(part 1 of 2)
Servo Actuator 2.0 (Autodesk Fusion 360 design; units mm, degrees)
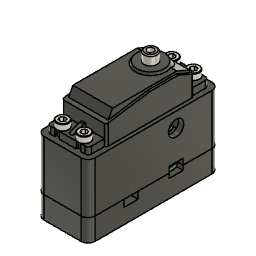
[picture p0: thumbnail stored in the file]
base_feature "Base Feature1"
base_feature "Base Feature1"
base_feature "Base Feature1"
base_feature "Base Feature1"
extrude "Extrude1" add of existing geometry blind 3.556
extrude "Extrude2" add of existing geometry blind 1
sketch "Sketch1" plane through (0, 0, 13.9918) normal (0, 0, -1) x axis (1, 0, 0)
  circle C1 centre (0, -10.25) radius 4
  circle C2 centre (0, -10.25) radius 8.7625
  dimension "d5" = 4.7625
extrude "Extrude1" new body sketch "Sketch1" along normal blind 5.675 (= "0.125 in + 2.5 mm")
extrude "Extrude3" add of existing geometry blind 3.175
combine "Combine1"
extrude "Extrude2" cut of existing geometry blind -4.7
sketch "Sketch2" plane through (0, 0, 24.9956) normal (0, 0, 1) x axis (-1, 0, 0)
  line L1 (0.8395, -12.0586) -> (1.9866, -10.4203)
  line L2 (-1.9866, -10.0797) -> (0.8395, -12.0586)
  line L3 (-0.8395, -8.4414) -> (-1.9866, -10.0797)
  line L4 (1.9866, -10.4203) -> (-0.8395, -8.4414)
  line L5 (-1.9866, -10.0797) -> (-0.8395, -8.4414)
  line L6 (0.8395, -12.0586) -> (-1.9866, -10.0797)
  line L7 (1.9866, -10.4203) -> (0.8395, -12.0586)
  line L8 (-0.8395, -8.4414) -> (1.9866, -10.4203)
  circle C1 centre (0, -10.25) radius 4
split "Split1"
copy_paste_bodies "CutPasteBodies1"
copy_paste_bodies "CutPasteBodies1"
component_from_bodies "Body->Comp1"
extrude "Extrude3" new body of existing geometry blind 2.5
delete_face "DeleteFace1"
component_from_bodies "Body->Comp1"
copy_paste "CutPaste1"
sketch "Sketch1" plane through (0, 0, 0) normal (0, 0, 1) x axis (1, 0, 0)
  line L1 (-7.25, -8.75) -> (7.25, -8.75)
  line L2 (-7.25, 8.75) -> (-7.25, -8.75)
  line L3 (7.25, 8.75) -> (-7.25, 8.75)
  line L4 (7.25, -8.75) -> (7.25, 8.75)
  line L5 (-7.25, 8.75) -> (7.25, -8.75)
  line L6 (7.25, 8.75) -> (-7.25, -8.75)
  line L7 (0, 8.75) -> (0, -8.75)
  line L8 (-2.5, -2.35) -> (2.5, -2.35)
  line L9 (-2.5, 1.45) -> (-2.5, -2.35)
  line L10 (2.5, 1.45) -> (-2.5, 1.45)
  line L11 (2.5, -2.35) -> (2.5, 1.45)
  line L12 (-2.5, 1.45) -> (2.5, -2.35)
  line L13 (2.5, 1.45) -> (-2.5, -2.35)
  line L14 (7.25, -0.45) -> (-7.25, -0.45)
  line L15 (3.75, -8.75) -> (7.25, -5.25)
  line L16 (-3.75, -8.75) -> (-7.25, -5.25)
  arc A1 centre (0, 0.1797) radius 8.5703 clockwise from (-7.25, 4.75) to (7.25, 4.75)
  circle C1 centre (6, -0.45) radius 1.5
  circle C2 centre (-6, -0.45) radius 1.5
  point P6 (0, 0)
  point P1 (0, 0)
  point P7 (0, -8.75)
  point P8 (0, 8.75)
  point P13 (0, -0.45)
  point P14 (-7.25, -0.45)
  point P15 (7.25, -0.45)
  point P16 (7.25, 4.75)
  point P17 (-7.25, 4.75)
  point P19 (7.25, 4.75)
  point P18 (-7.25, 4.75)
  point P21 (7.25, -5.25)
  point P22 (3.75, -8.75)
  point P23 (7.25, -5.25)
  point P24 (3.75, -8.75)
  point P25 (-7.25, -5.25)
  point P26 (-3.75, -8.75)
  point P27 (6, -0.45)
  point P2 (7.25, -8.75)
  point P5 (7.25, 8.75)
  horizontal L1
  perpendicular L1 L2
  parallel L1 L3
  parallel L2 L4
  coincident L5 P6
  coincident L6 P6
  coincident P1 P6
  midpoint L1 P7
  midpoint L3 P8
  horizontal L8
  perpendicular L8 L9
  parallel L8 L10
  parallel L9 L11
  coincident L12 P13
  coincident L13 P13
  coincident L7 P13
  coincident L2 P14
  coincident L4 P15
  perpendicular L4 L14
  coincident P13 L14
  coincident L4 P16
  symmetric L7 P16 P17
  coincident P8 A1
  tangent L3 A1
  coincident P16 P19
  coincident P17 P18
  coincident L4 P21
  coincident L1 P22
  coincident P21 P23
  coincident P22 P24
  symmetric L7 P23 P25
  symmetric L7 P24 P26
  coincident L14 P27
  symmetric L7 C1 C2
  dimension "d1_1" distance P2 P5 = 17.5
  dimension "d2_1" distance L2 L4 = 14.5
  dimension "d3_1" distance L1 L8 = 6.4
  dimension "d4_1" distance L3 L10 = 7.3
  dimension "d5_1" distance L9 L11 = 5
  dimension "d6_1" distance P5 P16 = 4
  dimension "d7_1" distance P2 P21 = 3.5
  dimension "d8_1" distance P2 P22 = 3.5
  dimension "d9_1" diameter C1 = 3
  dimension "d10_1" distance L11 P27 = 3.5 (= "2 mm + 1.5 mm")
extrude "Extrude1" new body sketch "Sketch1" profile of L1 L2 L4 L8 L9 L10 L11 A1 L15 L16 C1 C2 against normal blind 1.7 named "d11_1"
extrude "Extrude2" new body sketch "Sketch1" profile of L8 L9 L10 L11 along normal blind 1.5 named "d13_1"
position "Position1"
position "Position2"
position "Position3"
position "Position4"
copy_paste "CutPaste2"
work_plane "WorkPlane1" AlongDistance -21
split "Split1"
combine "Combine1"
split "Split1"
remove_body "RemoveBody2"
extrude "Extrude1" add of existing geometry blind 2.2
extrude "Extrude2" add of existing geometry blind 1
extrude "Extrude3" cut of existing geometry blind -0.2
extrude "Extrude4" add of existing geometry blind 0.2
work_plane "WorkPlane2"
extrude "Extrude4" cut of existing geometry blind -0.2063 (= "( 2 mm - ( ( 1 / 16 ) * 1 in ) ) / -2")
extrude "Extrude5" cut of existing geometry blind -0.2063 (= "( 2 mm - ( ( 1 / 16 ) * 1 in ) ) / -2")
extrude "Extrude5" add of existing geometry blind 0.2063 (= "( 2 mm - ( ( 1 / 16 ) * 1 in ) ) / 2")
extrude "Extrude6" add of existing geometry blind 0.2063 (= "( 2 mm - ( ( 1 / 16 ) * 1 in ) ) / 2")
sketch "Sketch4" plane through (0, 0, 28) normal (0, 0, -1) x axis (1, 0, 0)
  line L1 (-1.6037, -23.3708) -> (-1.6037, 14.6292)
  line L2 (-0.9037, -30.2208) -> (-0.9037, -24.3248)
  line L3 (2.4963, -31.7208) -> (0.5963, -31.7208)
  line L4 (2.4963, -31.0175) -> (2.4963, -31.7208)
  line L5 (4.4963, -31.7208) -> (4.4963, -31.0175)
  line L6 (12.2963, -31.7208) -> (4.4963, -31.7208)
  line L7 (12.2963, -31.0175) -> (12.2963, -31.7208)
  line L8 (14.2963, -31.7208) -> (14.2963, -31.0175)
  line L9 (16.1963, -31.7208) -> (14.2963, -31.7208)
  line L10 (17.6963, -24.3248) -> (17.6963, -30.2208)
  line L11 (18.3963, 14.6292) -> (18.3963, -23.3708)
  line L12 (17.6963, 21.4792) -> (17.6963, 15.5831)
  line L13 (14.2963, 22.9792) -> (16.1963, 22.9792)
  line L14 (14.2963, 22.2758) -> (14.2963, 22.9792)
  line L15 (12.2963, 22.9792) -> (12.2963, 22.2758)
  line L16 (4.4963, 22.9792) -> (12.2963, 22.9792)
  line L17 (4.4963, 22.2758) -> (4.4963, 22.9792)
  line L18 (2.4963, 22.9792) -> (2.4963, 22.2758)
  line L19 (0.5963, 22.9792) -> (2.4963, 22.9792)
  line L20 (-0.9037, 15.5831) -> (-0.9037, 21.4792)
  line L21 (15.3963, 15.6292) -> (1.3963, 15.6292)
  line L22 (1.3963, 15.6292) -> (15.3963, 15.6292)
  line L23 (8.3963, -2.0612) -> (8.3963, 15.6292)
  line L24 (22.9806, 14.6292) -> (-3.2785, 14.6292)
  arc A1 centre (-0.6037, 14.6292) radius 1 clockwise from (-1.6037, 14.6292) to (-0.9037, 15.5831)
  arc A2 centre (-0.6037, -23.3708) radius 1 clockwise from (-0.9037, -24.3248) to (-1.6037, -23.3708)
  arc A3 centre (0.5963, -30.2208) radius 1.5 clockwise from (0.5963, -31.7208) to (-0.9037, -30.2208)
  arc A4 centre (3.4963, -29.1708) radius 2.1 clockwise from (2.4963, -31.0175) to (4.4963, -31.0175)
  arc A5 centre (13.2963, -29.1708) radius 2.1 clockwise from (12.2963, -31.0175) to (14.2963, -31.0175)
  arc A6 centre (16.1963, -30.2208) radius 1.5 clockwise from (17.6963, -30.2208) to (16.1963, -31.7208)
  arc A7 centre (17.3963, -23.3708) radius 1 clockwise from (18.3963, -23.3708) to (17.6963, -24.3248)
  arc A8 centre (17.3963, 14.6292) radius 1 clockwise from (17.6963, 15.5831) to (18.3963, 14.6292)
  arc A9 centre (16.1963, 21.4792) radius 1.5 clockwise from (16.1963, 22.9792) to (17.6963, 21.4792)
  arc A10 centre (13.2963, 20.4292) radius 2.1 clockwise from (14.2963, 22.2758) to (12.2963, 22.2758)
  arc A11 centre (3.4963, 20.4292) radius 2.1 clockwise from (4.4963, 22.2758) to (2.4963, 22.2758)
  arc A12 centre (0.5963, 21.4792) radius 1.5 clockwise from (-0.9037, 21.4792) to (0.5963, 22.9792)
  circle C1 centre (8.3963, 6.1292) radius 8.5
  point P48 (8.3963, 15.6292)
  point P50 (8.3963, 6.1292)
  midpoint L21 P48
  perpendicular L21 L23
  coincident L23 P50
  perpendicular L1 L24
  tangent C1 L24
  dimension "d32" diameter C1 = 17
  dimension "d33" distance L22 L24 = 1
extrude "Extrude4" new body sketch "Sketch4" profile of C1 along normal blind 27.9908
extrude "Extrude5" add of existing geometry blind 0.5092 (= "41.5 mm - 1.6138110236220502 in")
copy_paste_bodies "CutPasteBodies1"
sketch "Sketch5" plane through (0, 0, 28) normal (0, 0, -1) x axis (1, 0, 0)
  line L1 (-1.6037, -23.3708) -> (-1.6037, 14.6292)
  line L2 (-0.9037, -30.2208) -> (-0.9037, -24.3248)
  line L3 (2.4963, -31.7208) -> (0.5963, -31.7208)
  line L4 (2.4963, -31.0175) -> (2.4963, -31.7208)
  line L5 (4.4963, -31.7208) -> (4.4963, -31.0175)
  line L6 (12.2963, -31.7208) -> (4.4963, -31.7208)
  line L7 (12.2963, -31.0175) -> (12.2963, -31.7208)
  line L8 (14.2963, -31.7208) -> (14.2963, -31.0175)
  line L9 (16.1963, -31.7208) -> (14.2963, -31.7208)
  line L10 (17.6963, -24.3248) -> (17.6963, -30.2208)
  line L11 (18.3963, 14.6292) -> (18.3963, -23.3708)
  line L12 (17.6963, 21.4792) -> (17.6963, 15.5831)
  line L13 (14.2963, 22.9792) -> (16.1963, 22.9792)
  line L14 (14.2963, 22.2758) -> (14.2963, 22.9792)
  line L15 (12.2963, 22.9792) -> (12.2963, 22.2758)
  line L16 (4.4963, 22.9792) -> (12.2963, 22.9792)
  line L17 (4.4963, 22.2758) -> (4.4963, 22.9792)
  line L18 (2.4963, 22.9792) -> (2.4963, 22.2758)
  line L19 (0.5963, 22.9792) -> (2.4963, 22.9792)
  line L20 (-0.9037, 15.5831) -> (-0.9037, 21.4792)
  arc A1 centre (-0.6037, 14.6292) radius 1 clockwise from (-1.6037, 14.6292) to (-0.9037, 15.5831)
  arc A2 centre (-0.6037, -23.3708) radius 1 clockwise from (-0.9037, -24.3248) to (-1.6037, -23.3708)
  arc A3 centre (0.5963, -30.2208) radius 1.5 clockwise from (0.5963, -31.7208) to (-0.9037, -30.2208)
  arc A4 centre (3.4963, -29.1708) radius 2.1 clockwise from (2.4963, -31.0175) to (4.4963, -31.0175)
  arc A5 centre (13.2963, -29.1708) radius 2.1 clockwise from (12.2963, -31.0175) to (14.2963, -31.0175)
  arc A6 centre (16.1963, -30.2208) radius 1.5 clockwise from (17.6963, -30.2208) to (16.1963, -31.7208)
  arc A7 centre (17.3963, -23.3708) radius 1 clockwise from (18.3963, -23.3708) to (17.6963, -24.3248)
  arc A8 centre (17.3963, 14.6292) radius 1 clockwise from (17.6963, 15.5831) to (18.3963, 14.6292)
  arc A9 centre (16.1963, 21.4792) radius 1.5 clockwise from (16.1963, 22.9792) to (17.6963, 21.4792)
  arc A10 centre (13.2963, 20.4292) radius 2.1 clockwise from (14.2963, 22.2758) to (12.2963, 22.2758)
  arc A11 centre (3.4963, 20.4292) radius 2.1 clockwise from (4.4963, 22.2758) to (2.4963, 22.2758)
  arc A12 centre (0.5963, 21.4792) radius 1.5 clockwise from (-0.9037, 21.4792) to (0.5963, 22.9792)
split "Split1"
remove_body "RemoveBody1"
delete_face "DeleteFace1"
delete_face "DeleteFace2"
sketch "Sketch6" plane through (0, 0, 28) normal (0, 0, -1) x axis (1, 0, 0)
  line L1 (-0.9037, -24.3248) -> (17.6963, 15.5831)
  line L2 (-0.9037, 15.5831) -> (17.6963, -24.3248)
  line L3 (-0.8337, -23.6158) -> (17.6263, -23.6158)
  line L4 (-0.8337, 14.8742) -> (-0.8337, -23.6158)
  line L5 (17.6263, 14.8742) -> (-0.8337, 14.8742)
  line L6 (17.6263, -23.6158) -> (17.6263, 14.8742)
  line L7 (-0.8337, 14.8742) -> (17.6263, -23.6158)
  line L8 (17.6263, 14.8742) -> (-0.8337, -23.6158)
  line L9 (-4.0087, 18.0492) -> (-4.0087, -26.7908)
  line L10 (20.8013, 18.0492) -> (-4.0087, 18.0492)
  line L11 (20.8013, -26.7908) -> (20.8013, 18.0492)
  line L12 (-4.0087, -26.7908) -> (20.8013, -26.7908)
  point P2 (17.6963, 15.5831)
  point P6 (17.6963, 15.5831)
  point P4 (-0.9037, -24.3248)
  point P7 (-0.9037, -24.3248)
  point P3 (17.6963, -24.3248)
  point P8 (17.6963, -24.3248)
  point P5 (-0.9037, 15.5831)
  point P9 (-0.9037, 15.5831)
  point P10 (8.3963, -4.3708)
  point P15 (8.3963, -4.3708)
  point P13 (-0.8337, 14.8742)
  point P14 (17.6263, 14.8742)
  point P11 (17.6263, -23.6158)
  coincident P2 P6
  coincident P4 P7
  coincident P3 P8
  coincident P5 P9
  midpoint L1 P10
  horizontal L3
  perpendicular L3 L4
  parallel L3 L5
  parallel L4 L6
  coincident L7 P15
  coincident L8 P15
  coincident P10 P15
  dimension "d38" distance P13 P14 = 18.46
  dimension "d39" distance P11 P14 = 38.49
  dimension "d44" = -3.175 (= "( -1 / 8 ) * 1 in")
split "Split2"
split "Split3"
delete_face "DeleteFace3"
extrude "Extrude1" cut of existing geometry blind -33.02
delete_face "DeleteFace4"
extrude "Extrude2" cut of existing geometry blind -29.21
extrude "Extrude6" new body sketch "Sketch6" profile of L3 L4 L5 L6 L9 L12 L10 L11 along normal blind 28.4988
work_plane "WorkPlane3" AlongDistance -1.6
split "Split2"
sketch "Sketch7" plane through (0, 0, 26.4) normal (0, 0, 1) x axis (-1, 0, 0)
  line L1 (0.8337, -23.6158) -> (0.8337, 14.8742)
  line L2 (-17.6263, -23.6158) -> (0.8337, -23.6158)
  line L3 (-17.6263, 14.8742) -> (-17.6263, -23.6158)
  line L4 (0.8337, 14.8742) -> (-17.6263, 14.8742)
  line L5 (4.0087, -26.7908) -> (-20.8013, -26.7908)
  line L6 (4.0087, 18.0492) -> (4.0087, -26.7908)
  line L7 (-20.8013, 18.0492) -> (4.0087, 18.0492)
  line L8 (-20.8013, -26.7908) -> (-20.8013, 18.0492)
  line L9 (-20.8013, 6.1292) -> (4.0087, 6.1292)
  line L10 (-20.8013, -1.8708) -> (4.0087, -1.8708)
  circle C1 centre (-8.3963, 6.1292) radius 8.5
  circle C2 centre (-8.3963, 6.1292) radius 8.75
  point P12 (4.0087, 6.1292)
  point P13 (-20.8013, 6.1292)
  point P14 (4.0087, -1.8708)
  point P15 (-20.8013, -1.8708)
  coincident L6 P12
  coincident L8 P13
  perpendicular L8 L9
  coincident L6 P14
  coincident L8 P15
  perpendicular L8 L10
  dimension "d48" = 0.25
  dimension "d51" distance L9 L10 = 8
extrude "Extrude7" add sketch "Sketch7" profile of L1 L3 L4 C2 L10 against normal blind 26.8988
extrude "Extrude8" cut sketch "Sketch7" profile of L4 C2 against normal blind 38.1
offset_faces "OffsetFaces1" distance 0.75
fillet "Fillet3" radius 1.651
split "Split3"
remove_body "RemoveBody5"
mirror "Mirror1" mirrorStitchTolerance 0.1016
combine "Combine2"
component_from_bodies "Body->Comp1"
copy_paste_bodies "CutPasteBodies1"
mirror "Mirror1" mirrorStitchTolerance 0.1016
align "Align1"
extrude "Extrude1" add of existing geometry blind 6.35
extrude "Extrude9" new body of existing geometry blind 19.9898
copy_paste_bodies "CutPasteBodies2"
copy_paste "CutPaste3"
copy_paste_bodies "CutPasteBodies2"
sketch "Sketch8" plane through (0, 0, 19.9956) normal (0, 0, -1) x axis (1, 0, 0)
  line L1 (0.3963, -22.3708) -> (0.3963, -3.3708)
  line L2 (16.3963, -22.3708) -> (0.3963, -22.3708)
  line L3 (16.3963, -3.3708) -> (16.3963, -22.3708)
  line L4 (0.3963, -3.3708) -> (16.3963, -3.3708)
  line L5 (1.5713, -6.5458) -> (1.5713, -21.1958)
  line L6 (15.2213, -6.5458) -> (1.5713, -6.5458)
  line L7 (15.2213, -21.1958) -> (15.2213, -6.5458)
  line L8 (1.5713, -21.1958) -> (15.2213, -21.1958)
  line L9 (-4.0087, 18.0492) -> (20.8013, 18.0492)
  line L10 (-4.0087, -26.7908) -> (-4.0087, 18.0492)
  line L11 (20.8013, -26.7908) -> (-4.0087, -26.7908)
  line L12 (20.8013, 18.0492) -> (20.8013, -26.7908)
  line L13 (16.8763, -22.8658) -> (16.8763, -3.2059)
  line L14 (-0.0837, -22.8658) -> (16.8763, -22.8658)
  line L15 (-0.0837, -3.2059) -> (-0.0837, -22.8658)
  circle C1 centre (8.3963, -14.6208) radius 8
  circle C2 centre (8.3963, -14.6208) radius 8
  arc A1 centre (8.3963, 6.1292) radius 8.75 clockwise from (1.4656, 0.788) to (15.327, 0.788)
  arc A2 centre (16.6347, -0.2198) radius 1.651 clockwise from (15.93, -1.7129) to (15.327, 0.788)
  arc A3 centre (15.2253, -3.2059) radius 1.651 clockwise from (15.93, -1.7129) to (16.8763, -3.2059)
  arc A4 centre (1.5673, -3.2059) radius 1.651 clockwise from (-0.0837, -3.2059) to (0.8626, -1.7129)
  arc A5 centre (0.1579, -0.2198) radius 1.651 clockwise from (1.4656, 0.788) to (0.8626, -1.7129)
  circle C3 centre (8.3963, 6.1292) radius 8.5
  circle C4 centre (8.3963, 6.1292) radius 8.75
  dimension "d72" = 0.25
extrude "Extrude10" new body sketch "Sketch8" profile of L1 L2 L3 L4 L5 L6 L7 L8 C1 C2 A2 A3 L13 L14 L15 A4 A5 C4 along normal blind 5.0038
sketch "Sketch9" plane through (0, 0, 14.9918) normal (0, 0, -1) x axis (1, 0, 0)
  line L1 (-0.0837, -22.8658) -> (-0.0837, -3.2059)
  line L2 (16.8763, -22.8658) -> (-0.0837, -22.8658)
  line L3 (16.8763, -3.2059) -> (16.8763, -22.8658)
  circle C1 centre (8.3963, -14.6208) radius 8
  arc A1 centre (15.2253, -3.2059) radius 1.651 clockwise from (15.93, -1.7129) to (16.8763, -3.2059)
  arc A2 centre (16.6347, -0.2198) radius 1.651 clockwise from (15.93, -1.7129) to (15.327, 0.788)
  arc A3 centre (8.3963, 6.1292) radius 8.75 clockwise from (15.327, 0.788) to (1.4656, 0.788)
  arc A4 centre (0.1579, -0.2198) radius 1.651 clockwise from (1.4656, 0.788) to (0.8626, -1.7129)
  arc A5 centre (1.5673, -3.2059) radius 1.651 clockwise from (-0.0837, -3.2059) to (0.8626, -1.7129)
  arc A6 centre (8.3963, 6.1292) radius 8.75 clockwise from (15.327, 0.788) to (1.4656, 0.788)
  arc A7 centre (8.3963, 6.1292) radius 11.1625 clockwise from (17.2379, -0.6847) to (-0.4452, -0.6847)
  dimension "d73" = 2.4125 (= "0.125 in - 0.0300196850393694 in")
extrude "Extrude11" add sketch "Sketch9" profile of A1 A2 A3 A4 A5 A6 A7 along normal blind 15.4906
combine "Combine3"
delete_face "DeleteFace1"
delete_face "DeleteFace2"
fillet "Fillet1" radius 4.7625
sketch "Sketch10" plane through (0, 0, 8.3168) normal (0, 0, -1) x axis (1, 0, 0)
  circle C1 centre (8.3963, -14.6208) radius 4
  circle C2 centre (8.3963, -14.6208) radius 8
  circle C3 centre (8.3963, -14.6208) radius 9.5875
  dimension "d78" = 1.5875 (= "( 1 / 16 ) * 1 in")
extrude "Extrude7" cut sketch "Sketch10" along normal blind 15.24 and against normal blind 6.6802
extrude "Extrude8" add of existing geometry blind 0.0052 (= "2.047E-04 in")
sketch "Sketch11" plane through (0, 0, 14.9918) normal (0, 0, -1) x axis (1, 0, 0)
  line L1 (16.8763, -22.8658) -> (13.2892, -22.8658)
  line L2 (16.8763, -19.0941) -> (16.8763, -22.8658)
  line L3 (16.8763, -9.3559) -> (16.8763, -10.1476)
  line L4 (-0.0837, -10.1476) -> (-0.0837, -9.3559)
  line L5 (-0.0837, -22.8658) -> (-0.0837, -19.0941)
  line L6 (3.5034, -22.8658) -> (-0.0837, -22.8658)
  circle C1 centre (8.3963, -14.6208) radius 8
  arc A1 centre (8.3963, -14.6208) radius 9.5875 clockwise from (16.8763, -10.1476) to (16.8763, -19.0941)
  arc A2 centre (12.1138, -9.3559) radius 4.7625 clockwise from (11.0021, -4.7249) to (16.8763, -9.3559)
  arc A3 centre (8.3963, 6.1292) radius 11.1625 clockwise from (11.0021, -4.7249) to (5.7906, -4.7249)
  arc A4 centre (4.6788, -9.3559) radius 4.7625 clockwise from (-0.0837, -9.3559) to (5.7906, -4.7249)
  arc A5 centre (8.3963, -14.6208) radius 9.5875 clockwise from (-0.0837, -19.0941) to (-0.0837, -10.1476)
  arc A6 centre (8.3963, -14.6208) radius 9.5875 clockwise from (13.2892, -22.8658) to (3.5034, -22.8658)
  circle C2 centre (8.3963, -14.6208) radius 9.5875
  dimension "d85" = 1.5875 (= "( 1 / 16 ) * 1 in")
extrude "Extrude9" add sketch "Sketch11" profile of L1 L2 L3 A2 A3 A4 L4 L5 L6 C2 along normal blind 15.494
extrude "Extrude10" cut of existing geometry blind -0.0034 (= "-1.339E-04 in")
extrude "Extrude3" cut of existing geometry blind -0.508
extrude "Extrude11" cut of existing geometry blind -0.508
extrude "Extrude4" cut of existing geometry blind -1
offset_faces "OffsetFaces1" distance 1.5875 (= "( 1 / 16 ) * 1 in")
split "Split2"
delete_face "DeleteFace3"
combine "Combine4"
split "Split3"
sketch "Sketch12" plane through (0, 0, 4.8168) normal (0, 0, 1) x axis (-1, 0, 0)
  line L1 (-4.6463, -6.3208) -> (-1.1463, -9.8208)
  line L2 (-12.1463, -6.3208) -> (-4.6463, -6.3208)
  line L3 (-15.6463, -9.8208) -> (-12.1463, -6.3208)
  line L4 (-15.6463, -13.7917) -> (-15.6463, -9.8208)
  line L5 (-15.6463, -19.8208) -> (-15.6463, -15.45)
  line L6 (-1.1463, -15.45) -> (-1.1463, -19.8208)
  line L7 (-1.1463, -9.8208) -> (-1.1463, -13.7917)
  line L8 (-12.1463, -6.3208) -> (-15.6463, -9.8208)
  line L9 (-4.6463, -6.3208) -> (-12.1463, -6.3208)
  line L10 (-4.6463, -6.3208) -> (-1.1463, -9.8208)
  line L11 (-15.6463, -9.8208) -> (-15.6463, -19.8208)
  line L12 (-1.1463, -9.8208) -> (-1.1463, -19.8208)
  line L13 (-0.8963, -9.7173) -> (-0.8963, -19.8925)
  line L14 (-4.5428, -6.0708) -> (-0.8963, -9.7173)
  line L15 (-4.5428, -6.0708) -> (-12.2499, -6.0708)
  line L16 (-12.2499, -6.0708) -> (-15.8963, -9.7173)
  line L17 (-15.8963, -9.7173) -> (-15.8963, -19.8925)
  arc A1 centre (-14.3963, -14.6208) radius 1.5 clockwise from (-15.6463, -13.7917) to (-15.6463, -15.45)
  arc A2 centre (-8.3963, -15.2505) radius 8.5703 clockwise from (-1.1463, -19.8208) to (-15.6463, -19.8208)
  arc A3 centre (-2.3963, -14.6208) radius 1.5 clockwise from (-1.1463, -15.45) to (-1.1463, -13.7917)
  arc A4 centre (-8.3963, -15.2505) radius 8.5703 clockwise from (-1.1463, -19.8208) to (-15.6463, -19.8208)
  arc A5 centre (-8.3963, -15.2505) radius 8.8203 clockwise from (-0.8963, -19.8925) to (-15.8963, -19.8925)
  circle C1 centre (-8.3963, -14.6208) radius 9.5875
  point P15 (-15.6463, -19.8208)
  point P22 (-15.6463, -19.8208)
  point P18 (-15.6463, -9.8208)
  point P23 (-15.6463, -9.8208)
  point P16 (-1.1463, -19.8208)
  point P24 (-1.1463, -19.8208)
  point P21 (-1.1463, -9.8208)
  point P25 (-1.1463, -9.8208)
  coincident P15 P22
  coincident P18 P23
  coincident P16 P24
  coincident P21 P25
  dimension "d97" = 0.25
extrude "Extrude12" add sketch "Sketch12" profile of A5 L13 L14 L15 L16 L17 C1 against normal blind 4.8006
extrude "Extrude13" add of existing geometry blind 0.007 (= "2.756E-04 in")
split "Split4"
delete_face "DeleteFace4"
delete_face "DeleteFace5"
combine "Combine5"
extrude "Extrude14" add of existing geometry blind 1.4986
extrude "Extrude15" add of existing geometry blind 0.0014 (= "5.512E-05 in")
sketch "Sketch13" plane through (0, 0, 6.3168) normal (0, 0, 1) x axis (-1, 0, 0)
  line L1 (-15.8963, -9.7173) -> (-15.8963, -19.8925)
  line L2 (-12.2499, -6.0708) -> (-15.8963, -9.7173)
  line L3 (-4.5428, -6.0708) -> (-12.2499, -6.0708)
  line L4 (-0.8963, -9.7173) -> (-4.5428, -6.0708)
  line L5 (-0.8963, -19.8925) -> (-0.8963, -9.7173)
  line L6 (5.5962, 19.6367) -> (5.5962, -28.3783)
  line L7 (-22.3888, 19.6367) -> (5.5962, 19.6367)
  line L8 (-22.3888, -28.3783) -> (-22.3888, 19.6367)
  line L9 (5.5962, -28.3783) -> (-22.3888, -28.3783)
  line L10 (-3.6338, -52.7208) -> (-13.1588, -52.7208)
  line L11 (-3.6338, 23.4792) -> (-3.6338, -52.7208)
  line L12 (-13.1588, 23.4792) -> (-3.6338, 23.4792)
  line L13 (-13.1588, -52.7208) -> (-13.1588, 23.4792)
  line L14 (-3.6338, 23.4792) -> (-13.1588, -52.7208)
  line L15 (-13.1588, 23.4792) -> (-3.6338, -52.7208)
  arc A1 centre (-8.3963, -15.2505) radius 8.8203 clockwise from (-0.8963, -19.8925) to (-15.8963, -19.8925)
  circle C1 centre (-8.3963, 6.1292) radius 8.75
  circle C2 centre (-8.3963, -14.6208) radius 4
  point P19 (-8.3963, -14.6208)
  point P14 (-8.3963, -14.6208)
  point P15 (-13.1588, -52.7208)
  point P16 (-3.6338, -52.7208)
  point P18 (-13.1588, 23.4792)
  horizontal L10
  perpendicular L10 L11
  parallel L10 L12
  parallel L11 L13
  coincident L14 P19
  coincident L15 P19
  coincident P14 P19
  dimension "d106" distance P15 P16 = 9.525
  dimension "d107" distance P15 P18 = 76.2
extrude "Extrude16" cut sketch "Sketch13" profile of A1 L9 L11 L13 against normal blind 3.2004
extrude "Extrude17" cut sketch "Sketch13" profile of L7 C1 L11 L13 against normal blind 5.3086
extrude "Extrude18" cut of existing geometry blind -0.0002 (= "-7.873E-06 in")
extrude "Extrude19" add of existing geometry blind 0.0004 (= "1.574E-05 in")
combine "Combine1"
offset_faces "OffsetFaces2" distance 0.7937 (= "( 1 / 32 ) * 1 in")
extrude "Extrude20" add of existing geometry blind 2.175 (= "0.125 in - 1 mm")
sketch "Sketch14" plane through (0, 0, 28) normal (0, 0, 1) x axis (-1, 0, 0)
  line L1 (0.8337, 14.8742) -> (-17.6263, 14.8742)
  line L2 (0.8337, -23.6158) -> (0.8337, 14.8742)
  line L3 (-17.6263, -23.6158) -> (0.8337, -23.6158)
  line L4 (-17.6263, 14.8742) -> (-17.6263, -23.6158)
  line L5 (-22.3888, -28.3783) -> (-22.3888, 19.6367)
  line L6 (5.5962, -28.3783) -> (-22.3888, -28.3783)
  line L7 (5.5962, 19.6367) -> (5.5962, -28.3783)
  line L8 (-22.3888, 19.6367) -> (5.5962, 19.6367)
  line L9 (-17.6963, 15.5831) -> (0.9037, 15.5831)
  line L10 (0.9037, 15.5831) -> (-17.6963, 15.5831)
  line L11 (-18.3963, -23.3708) -> (-18.3963, 14.6292)
  line L12 (-18.3963, -17.3601) -> (-18.3963, -23.3708)
  line L13 (-18.3963, -4.3708) -> (-18.3963, -17.3601)
  line L14 (-18.3963, 14.6292) -> (-18.3963, -4.3708)
  line L15 (1.6037, 14.6292) -> (1.6037, -23.3708)
  line L16 (1.6037, -4.3708) -> (1.6037, 14.6292)
  line L17 (1.6037, -17.3601) -> (1.6037, -4.3708)
  line L18 (1.6037, -23.3708) -> (1.6037, -17.3601)
  line L19 (-17.6963, -24.3248) -> (0.9037, -24.3248)
  line L20 (0.9037, -24.3248) -> (-17.6963, -24.3248)
  arc A1 centre (-17.3963, 14.6292) radius 1 clockwise from (-18.3963, 14.6292) to (-17.6963, 15.5831)
  arc A2 centre (-17.3963, 14.6292) radius 1 clockwise from (-18.3963, 14.6292) to (-17.6963, 15.5831)
  arc A3 centre (0.6037, 14.6292) radius 1 clockwise from (0.9037, 15.5831) to (1.6037, 14.6292)
  arc A4 centre (0.6037, 14.6292) radius 1 clockwise from (0.9037, 15.5831) to (1.6037, 14.6292)
  arc A5 centre (0.6037, -23.3708) radius 1 clockwise from (1.6037, -23.3708) to (0.9037, -24.3248)
  arc A6 centre (0.6037, -23.3708) radius 1 clockwise from (1.6037, -23.3708) to (0.9037, -24.3248)
  arc A7 centre (-17.3963, -23.3708) radius 1 clockwise from (-17.6963, -24.3248) to (-18.3963, -23.3708)
  arc A8 centre (-17.3963, -23.3708) radius 1 clockwise from (-17.6963, -24.3248) to (-18.3963, -23.3708)
extrude "Extrude21" add sketch "Sketch14" profile of L5 L6 L7 L8 A1 A2 L9 L10 L11 L12 L13 L14 A3 A4 L15 L16 L17 L18 A5 A6 L19 L20 A7 A8 along normal blind 13.0048
split "Split5"
extrude "Extrude22" add of existing geometry blind 2
remove_body "RemoveBody3"
copy_paste "CutPaste1"
copy_paste_bodies "CutPasteBodies1"
remove_instance "RemoveInstance2"
split "Split6"
remove_body "RemoveBody4"
combine "Combine1"
offset_faces "OffsetFaces3" distance 4.93 (= "0.1315944881889787 in + ( 1 / 16 ) * 1 in")
sketch "Sketch16" plane through (0, 0, 28) normal (0, 0, 1) x axis (-1, 0, 0)
  line L1 (5.5962, 24.5667) -> (5.5962, -33.3083)
  line L2 (-22.3888, 24.5667) -> (5.5962, 24.5667)
  line L3 (-22.3888, -33.3083) -> (-22.3888, 24.5667)
  line L4 (5.5962, -33.3083) -> (-22.3888, -33.3083)
  line L5 (0.8337, 14.8742) -> (-17.6263, 14.8742)
  line L6 (0.8337, -23.6158) -> (0.8337, 14.8742)
  line L7 (-17.6263, -23.6158) -> (0.8337, -23.6158)
  line L8 (-17.6263, 14.8742) -> (-17.6263, -23.6158)
  arc A1 centre (-3.4963, 20.4292) radius 2.1 clockwise from (-2.4963, 22.2758) to (-4.4963, 22.2758)
  circle C1 centre (-3.4963, 20.4292) radius 1.5
  concentric A1 C1
  dimension "d141" diameter C1 = 3
work_plane "WorkPlane5"
chamfer "Chamfer1" distance 6.35
split "Split7"
sketch "Sketch17" plane through (0, 0, 28) normal (0, 0, 1) x axis (-1, 0, 0)
  line L1 (0.8337, 14.8742) -> (-17.6263, 14.8742)
  line L2 (0.8337, -23.6158) -> (0.8337, 14.8742)
  line L3 (-17.6263, -23.6158) -> (0.8337, -23.6158)
  line L4 (-17.6263, 14.8742) -> (-17.6263, -23.6158)
  line L5 (5.5962, -26.9583) -> (-0.7538, -33.3083)
  line L6 (5.5962, 18.2167) -> (5.5962, -26.9583)
  line L7 (-0.7538, 24.5667) -> (5.5962, 18.2167)
  line L8 (-16.0388, 24.5667) -> (-0.7538, 24.5667)
  line L9 (-22.3888, 18.2167) -> (-16.0388, 24.5667)
  line L10 (-22.3888, -26.9583) -> (-22.3888, 18.2167)
  line L11 (-16.0388, -33.3083) -> (-22.3888, -26.9583)
  line L12 (-0.7538, -33.3083) -> (-16.0388, -33.3083)
  arc A1 centre (-3.4963, 20.4292) radius 2.1 clockwise from (-2.4963, 22.2758) to (-4.4963, 22.2758)
  circle C1 centre (-3.4963, 20.4292) radius 2.2
  concentric A1 C1
  dimension "d149" diameter C1 = 4.4
extrude "Extrude26" cut sketch "Sketch17" profile of C1 against normal blind 6
mirror "Mirror4" mirrorStitchTolerance 0.1016
mirror "Mirror5" mirrorStitchTolerance 0.1016
sketch "Sketch1" plane through (0, 0, 0) normal (0, 0, 1) x axis (1, 0, 0)
  circle C1 centre (0, 0) radius 2.45
  circle C2 centre (0, 0) radius 1.5
  circle C3 centre (0, 0) radius 1.95
  point P1 (0, 0)
  point P2 (0, 0)
  coincident P1 P2
  concentric C1 C2
  concentric C1 C3
  dimension "d1_2" diameter C1 = 4.9
  dimension "d2_2" diameter C2 = 3
  dimension "d3_2" diameter C3 = 3.9
extrude "Extrude1" new body sketch "Sketch1" distance 0.7 (= "( 1.4 / 2 ) * 1 mm") named "d4_2"
extrude "Extrude2" add sketch "Sketch1" profile of C2 C3 distance 3.3 (= "5 mm - 1.7 mm") named "d6_2"
extrude "Extrude3" of existing geometry blind 1.7 named "d9_2"
extrude "Extrude4" add of existing geometry blind 1.7 named "d11_2"
mirror "Mirror1" mirrorStitchTolerance 0.1 named "d14_1"
extrude "Extrude5" new body sketch "Sketch1" profile of C2 C3 distance 3 named "d15_1"
extrude "Extrude6" sketch "Sketch1" blind -1.8 named "d18_1"
mirror "Mirror2" mirrorStitchTolerance 0.1 named "d21_1"
move "Move1"
copy_paste "CutPaste4"
remove_body "RemoveBody1"
align "Align1"
mirror "Mirror3" mirrorStitchTolerance 0.1016
mirror "Mirror4" mirrorStitchTolerance 0.1016
base_feature "Base Feature1"
base_feature "Base Feature1"
base_feature "Base Feature1"
base_feature "Base Feature1"
base_feature "Base Feature1"
base_feature "Base Feature1"
copy_paste "CutPaste5"
remove_instance "RemoveInstance4"
align "Align1"
mirror "Mirror1" mirrorStitchTolerance 0.1016
mirror "Mirror2" mirrorStitchTolerance 0.1016
sketch "Sketch18" plane through (0, 0, -2.1658) normal (0, 0, -1) x axis (1, 0, 0)
  line L1 (0.7538, -33.3083) -> (-5.5962, -26.9583)
  line L2 (16.0388, -33.3083) -> (0.7538, -33.3083)
  line L3 (22.3888, -26.9583) -> (16.0388, -33.3083)
  line L4 (22.3888, 18.2167) -> (22.3888, -26.9583)
  line L5 (16.0388, 24.5667) -> (22.3888, 18.2167)
  line L6 (0.7538, 24.5667) -> (16.0388, 24.5667)
  line L7 (-5.5962, 18.2167) -> (0.7538, 24.5667)
  line L8 (-5.5962, -26.9583) -> (-5.5962, 18.2167)
  line L9 (-5.5962, -26.9583) -> (0.7538, -33.3083)
  line L10 (-5.5962, 18.2167) -> (-5.5962, -26.9583)
  line L11 (0.7538, 24.5667) -> (-5.5962, 18.2167)
  line L12 (3.6338, 24.5667) -> (0.7538, 24.5667)
  line L13 (3.6338, 13.4695) -> (3.6338, 24.5667)
  line L14 (13.1588, 24.5667) -> (13.1588, 13.4695)
  line L15 (16.0388, 24.5667) -> (13.1588, 24.5667)
  line L16 (22.3888, 18.2167) -> (16.0388, 24.5667)
  line L17 (22.3888, -26.9583) -> (22.3888, 18.2167)
  line L18 (16.0388, -33.3083) -> (22.3888, -26.9583)
  line L19 (13.1588, -33.3083) -> (16.0388, -33.3083)
  line L20 (13.1588, -22.6746) -> (13.1588, -33.3083)
  line L21 (15.8963, -9.7173) -> (15.8963, -19.8925)
  line L22 (12.2499, -6.0708) -> (15.8963, -9.7173)
  line L23 (4.5428, -6.0708) -> (12.2499, -6.0708)
  line L24 (0.8963, -9.7173) -> (4.5428, -6.0708)
  line L25 (0.8963, -19.8925) -> (0.8963, -9.7173)
  line L26 (3.6338, -33.3083) -> (3.6338, -22.6746)
  line L27 (0.7538, -33.3083) -> (3.6338, -33.3083)
  line L28 (-5.5962, -26.9583) -> (22.3888, 18.2167)
  line L29 (-5.5962, 18.2167) -> (22.3888, -26.9583)
  line L30 (-1.1287, -25.0083) -> (17.9213, -25.0083)
  line L31 (-1.1287, 16.2667) -> (-1.1287, -25.0083)
  line L32 (17.9213, 16.2667) -> (-1.1287, 16.2667)
  line L33 (17.9213, -25.0083) -> (17.9213, 16.2667)
  line L34 (-1.1287, 16.2667) -> (17.9213, -25.0083)
  line L35 (17.9213, 16.2667) -> (-1.1287, -25.0083)
  arc A1 centre (8.3963, 6.1292) radius 8.75 clockwise from (13.1588, 13.4695) to (3.6338, 13.4695)
  arc A2 centre (8.3963, -15.2505) radius 8.8203 clockwise from (15.8963, -19.8925) to (13.1588, -22.6746)
  arc A3 centre (8.3963, -15.2505) radius 8.8203 clockwise from (3.6338, -22.6746) to (0.8963, -19.8925)
  circle C1 centre (17.9213, 16.2667) radius 2.2
  point P20 (22.3888, 18.2167)
  point P34 (22.3888, 18.2167)
  point P11 (-5.5962, -26.9583)
  point P35 (-5.5962, -26.9583)
  point P21 (22.3888, -26.9583)
  point P36 (22.3888, -26.9583)
  point P12 (-5.5962, 18.2167)
  point P37 (-5.5962, 18.2167)
  point P38 (8.3963, -4.3708)
  point P43 (8.3963, -4.3708)
  point P42 (17.9213, 16.2667)
  point P44 (17.9213, 16.2667)
  point P39 (17.9213, -25.0083)
  point P41 (-1.1287, 16.2667)
  coincident P20 P34
  coincident P11 P35
  coincident P21 P36
  coincident P12 P37
  midpoint L29 P38
  horizontal L30
  perpendicular L30 L31
  parallel L30 L32
  parallel L31 L33
  coincident L34 P43
  coincident L35 P43
  coincident P38 P43
  coincident P42 P44
  dimension "d164" distance P39 P42 = 41.275
  dimension "d165" distance P41 P42 = 19.05
  dimension "d166" diameter C1 = 4.4
extrude "Extrude27" cut sketch "Sketch18" profile of C1 against normal blind 6
mirror "Mirror6" mirrorStitchTolerance 0.1016
mirror "Mirror7" mirrorStitchTolerance 0.1016
copy_paste_bodies "CopyPasteBodies1"
move "Move2"
align "Align2"
mirror "Mirror5" mirrorStitchTolerance 0.1016
mirror "Mirror6" mirrorStitchTolerance 0.1016
offset_faces "OffsetFaces4" distance 0.7937 (= "( 1 / 32 ) * 1 in")
delete_face "DeleteFace8"
delete_face "DeleteFace9"
delete_face "DeleteFace10"
delete_face "DeleteFace11"
delete_face "DeleteFace12"
delete_face "DeleteFace13"
delete_face "DeleteFace14"
delete_face "DeleteFace15"
chamfer "Chamfer2" distance 6.35
sketch "Sketch19" plane through (0, 0, 8.3168) normal (0, 0, 1) x axis (-1, 0, 0)
  line L1 (-16.8326, -34.1021) -> (-23.1826, -27.7521)
  line L2 (-13.1588, -34.1021) -> (-16.8326, -34.1021)
  line L3 (-13.1588, -22.6746) -> (-13.1588, -34.1021)
  line L4 (-15.8963, -9.7173) -> (-15.8963, -19.8925)
  line L5 (-12.2499, -6.0708) -> (-15.8963, -9.7173)
  line L6 (-4.5428, -6.0708) -> (-12.2499, -6.0708)
  line L7 (-0.8963, -9.7173) -> (-4.5428, -6.0708)
  line L8 (-0.8963, -19.8925) -> (-0.8963, -9.7173)
  line L9 (-3.6338, -34.1021) -> (-3.6338, -22.6746)
  line L10 (0.0399, -34.1021) -> (-3.6338, -34.1021)
  line L11 (6.3899, -27.7521) -> (0.0399, -34.1021)
  line L12 (6.3899, 19.0104) -> (6.3899, -27.7521)
  line L13 (0.0399, 25.3604) -> (6.3899, 19.0104)
  line L14 (-3.6338, 25.3604) -> (0.0399, 25.3604)
  line L15 (-3.6338, 13.4695) -> (-3.6338, 25.3604)
  line L16 (-13.1588, 25.3604) -> (-13.1588, 13.4695)
  line L17 (-16.8326, 25.3604) -> (-13.1588, 25.3604)
  line L18 (-23.1826, 19.0104) -> (-16.8326, 25.3604)
  line L19 (-23.1826, -27.7521) -> (-23.1826, 19.0104)
  line L20 (-14.7463, -14.6208) -> (-2.0463, -14.6208)
  arc A1 centre (-8.3963, -15.2505) radius 8.8203 clockwise from (-13.1588, -22.6746) to (-15.8963, -19.8925)
  arc A2 centre (-8.3963, -15.2505) radius 8.8203 clockwise from (-0.8963, -19.8925) to (-3.6338, -22.6746)
  arc A3 centre (-8.3963, 6.1292) radius 8.75 clockwise from (-3.6338, 13.4695) to (-13.1588, 13.4695)
  circle C1 centre (-8.3963, -14.6208) radius 4
  arc A4 centre (-7.6763, -14.8049) radius 9.6671 clockwise from (-15.8963, -19.8925) to (-15.8963, -9.7173)
  arc A5 centre (-9.1163, -14.8049) radius 9.6671 clockwise from (-0.8963, -9.7173) to (-0.8963, -19.8925)
  point P26 (-8.3963, -14.6208)
  point P29 (-8.3963, -14.6208)
  point P6 (-15.8963, -19.8925)
  point P31 (-15.8963, -19.8925)
  point P8 (-15.8963, -9.7173)
  point P30 (-15.8963, -9.7173)
  point P11 (-0.8963, -9.7173)
  point P34 (-0.8963, -9.7173)
  point P12 (-0.8963, -19.8925)
  point P33 (-0.8963, -19.8925)
  point P27 (-2.0463, -14.6208)
  point P28 (-14.7463, -14.6208)
  perpendicular L4 L20
  coincident P26 P29
  midpoint L20 P29
  coincident P6 P31
  coincident P8 P30
  coincident P11 P34
  coincident P12 P33
  tangent A1 A4
  tangent A2 A5
  dimension "d179" distance P27 P28 = 12.7
extrude "Extrude28" cut sketch "Sketch19" profile of L4 L8 A4 A5 against normal blind 2
sketch "Sketch20" plane through (0, 0, 26.4) normal (0, 0, 1) x axis (-1, 0, 0)
  line L1 (-17.6263, 14.8742) -> (-8.6921, 14.8742)
  line L2 (-17.6263, -23.6158) -> (-17.6263, 14.8742)
  line L3 (0.8337, -23.6158) -> (-17.6263, -23.6158)
  line L4 (0.8337, 14.8742) -> (0.8337, -23.6158)
  line L5 (-8.1005, 14.8742) -> (0.8337, 14.8742)
  line L6 (0.0837, -22.8658) -> (0.0837, -3.2059)
  line L7 (-16.8763, -22.8658) -> (0.0837, -22.8658)
  line L8 (-16.8763, -3.2059) -> (-16.8763, -22.8658)
  line L9 (-16.8763, 12.104) -> (-16.8763, -3.2059)
  line L10 (0.0837, 11.1729) -> (0.0837, -3.2059)
  arc A1 centre (-8.3963, 6.1292) radius 8.75 clockwise from (-8.1005, 14.8742) to (-1.4656, 0.788)
  arc A2 centre (-0.1579, -0.2198) radius 1.651 clockwise from (-0.8626, -1.7129) to (-1.4656, 0.788)
  arc A3 centre (-1.5673, -3.2059) radius 1.651 clockwise from (-0.8626, -1.7129) to (0.0837, -3.2059)
  arc A4 centre (-15.2253, -3.2059) radius 1.651 clockwise from (-16.8763, -3.2059) to (-15.93, -1.7129)
  arc A5 centre (-16.6347, -0.2198) radius 1.651 clockwise from (-15.327, 0.788) to (-15.93, -1.7129)
  arc A6 centre (-8.3963, 6.1292) radius 8.75 clockwise from (-15.327, 0.788) to (-8.6921, 14.8742)
  point P16 (-16.8763, -3.2059)
  point P21 (-16.8763, -3.2059)
  point P12 (0.0837, -3.2059)
  point P23 (0.0837, -3.2059)
  coincident P16 P21
  tangent A4 L9
  coincident P12 P23
  tangent A3 L10
extrude "Extrude29" cut sketch "Sketch20" profile of A1 A2 A3 A4 A5 A6 L9 L10 against normal blind 6.4008
extrude "Extrude30" cut of existing geometry blind -0.0036 (= "-1.417E-04 in")
component_from_bodies "Body->Comp1"
component_from_bodies "Body->Comp2"
component_from_bodies "Body->Comp3"
sketch "Sketch21" plane through (0, 0, 8.3168) normal (0, 0, 1) x axis (-1, 0, 0)
  line L1 (-3.6338, -34.1021) -> (-3.6338, -22.6746)
  line L2 (0.0399, -34.1021) -> (-3.6338, -34.1021)
  line L3 (6.3899, -27.7521) -> (0.0399, -34.1021)
  line L4 (6.3899, 19.0104) -> (6.3899, -27.7521)
  line L5 (0.0399, 25.3604) -> (6.3899, 19.0104)
  line L6 (-3.6338, 25.3604) -> (0.0399, 25.3604)
  line L7 (-3.6338, 13.4695) -> (-3.6338, 25.3604)
  line L8 (-13.1588, 25.3604) -> (-13.1588, 13.4695)
  line L9 (-16.8326, 25.3604) -> (-13.1588, 25.3604)
  line L10 (-23.1826, 19.0104) -> (-16.8326, 25.3604)
  line L11 (-23.1826, -27.7521) -> (-23.1826, 19.0104)
  line L12 (-16.8326, -34.1021) -> (-23.1826, -27.7521)
  line L13 (-13.1588, -34.1021) -> (-16.8326, -34.1021)
  line L14 (-13.1588, -22.6746) -> (-13.1588, -34.1021)
  line L15 (-12.2499, -6.0708) -> (-15.8963, -9.7173)
  line L16 (-4.5428, -6.0708) -> (-12.2499, -6.0708)
  line L17 (-0.8963, -9.7173) -> (-4.5428, -6.0708)
  line L18 (-0.8963, -9.7173) -> (-0.8963, -19.8925)
  line L19 (-4.5428, -6.0708) -> (-0.8963, -9.7173)
  line L20 (-12.2499, -6.0708) -> (-4.5428, -6.0708)
  line L21 (-15.8963, -9.7173) -> (-12.2499, -6.0708)
  line L22 (-15.8963, -19.8925) -> (-15.8963, -9.7173)
  line L23 (-13.1588, -34.1021) -> (-13.1588, -22.6746)
  line L24 (-3.6338, -34.1021) -> (-13.1588, -34.1021)
  line L25 (-3.6338, -22.6746) -> (-3.6338, -34.1021)
  arc A1 centre (-9.1163, -14.8049) radius 9.6671 clockwise from (-0.8963, -9.7173) to (-0.8963, -19.8925)
  arc A2 centre (-8.3963, -15.2505) radius 8.8203 clockwise from (-0.8963, -19.8925) to (-3.6338, -22.6746)
  arc A3 centre (-8.3963, 6.1292) radius 8.75 clockwise from (-3.6338, 13.4695) to (-13.1588, 13.4695)
  arc A4 centre (-8.3963, -15.2505) radius 8.8203 clockwise from (-13.1588, -22.6746) to (-15.8963, -19.8925)
  arc A5 centre (-7.6763, -14.8049) radius 9.6671 clockwise from (-15.8963, -19.8925) to (-15.8963, -9.7173)
  arc A6 centre (-8.3963, -15.2505) radius 8.5703 clockwise from (-1.1463, -19.8208) to (-15.6463, -19.8208)
  arc A7 centre (-8.3963, -15.2505) radius 8.8203 clockwise from (-3.6338, -22.6746) to (-13.1588, -22.6746)
  arc A8 centre (-8.3963, -15.2505) radius 8.8203 clockwise from (-13.1588, -22.6746) to (-15.8963, -19.8925)
  arc A9 centre (-8.3963, -15.2505) radius 8.8203 clockwise from (-0.8963, -19.8925) to (-3.6338, -22.6746)
  point P22 (-13.1588, -22.6746)
  point P32 (-13.1588, -22.6746)
  point P5 (-3.6338, -22.6746)
  point P31 (-3.6338, -22.6746)
  coincident P22 P32
  coincident P5 P31
  tangent A4 A7
extrude "Extrude1" add sketch "Sketch21" profile of L1 L14 A7 L23 L24 L25 against normal blind 5.207
move_face "MoveFace1"
position "Position5"
sketch "Sketch22" plane through (0, 0, 8.3168) normal (0, 0, 1) x axis (-1, 0, 0)
  line L1 (0.1537, -10.7673) -> (-3.4928, -7.1208)
  line L2 (0.1537, -18.4744) -> (0.1537, -10.7673)
  line L3 (-3.4928, -22.1208) -> (0.1537, -18.4744)
  line L4 (0.0399, -34.1021) -> (-16.8326, -34.1021)
  line L5 (6.3899, -27.7521) -> (0.0399, -34.1021)
  line L6 (6.3899, 19.0104) -> (6.3899, -27.7521)
  line L7 (0.0399, 25.3604) -> (6.3899, 19.0104)
  line L8 (-3.6338, 25.3604) -> (0.0399, 25.3604)
  line L9 (-3.6338, 13.4695) -> (-3.6338, 25.3604)
  line L10 (-13.1588, 25.3604) -> (-13.1588, 13.4695)
  line L11 (-16.8326, 25.3604) -> (-13.1588, 25.3604)
  line L12 (-23.1826, 19.0104) -> (-16.8326, 25.3604)
  line L13 (-23.1826, -27.7521) -> (-23.1826, 19.0104)
  line L14 (-16.8326, -34.1021) -> (-23.1826, -27.7521)
  line L15 (-10.2963, -17.1208) -> (-10.2963, -12.1208)
  line L16 (-6.4963, -17.1208) -> (-10.2963, -17.1208)
  line L17 (-6.4963, -12.1208) -> (-6.4963, -17.1208)
  line L18 (-10.2963, -12.1208) -> (-6.4963, -12.1208)
  line L19 (-3.6338, 25.3604) -> (-3.6338, 13.4695)
  line L20 (-13.1588, 25.3604) -> (-3.6338, 25.3604)
  line L21 (-13.1588, 13.4695) -> (-13.1588, 25.3604)
  line L22 (-6.4963, -12.1208) -> (-10.2963, -17.1208)
  line L23 (-6.4963, -17.1208) -> (-10.2963, -12.1208)
  line L24 (11.7059, -11.4458) -> (-28.4985, -11.4458)
  line L25 (11.7059, -17.7958) -> (11.7059, -11.4458)
  line L26 (-28.4985, -17.7958) -> (11.7059, -17.7958)
  line L27 (-28.4985, -11.4458) -> (-28.4985, -17.7958)
  line L28 (11.7059, -17.7958) -> (-28.4985, -11.4458)
  line L29 (-28.4985, -17.7958) -> (11.7059, -11.4458)
  line L30 (14.7067, 9.3042) -> (-31.4993, 9.3042)
  line L31 (14.7067, 2.9542) -> (14.7067, 9.3042)
  line L32 (-31.4993, 2.9542) -> (14.7067, 2.9542)
  line L33 (-31.4993, 9.3042) -> (-31.4993, 2.9542)
  line L34 (14.7067, 2.9542) -> (-31.4993, 9.3042)
  line L35 (-31.4993, 2.9542) -> (14.7067, 9.3042)
  arc A1 centre (-9.026, -14.6208) radius 8.8203 clockwise from (-13.668, -22.1208) to (-13.668, -7.1208)
  arc A2 centre (-8.5804, -15.3408) radius 9.6671 clockwise from (-13.668, -7.1208) to (-3.4928, -7.1208)
  arc A3 centre (-8.5804, -13.9008) radius 9.6671 clockwise from (-3.4928, -22.1208) to (-13.668, -22.1208)
  arc A4 centre (-8.3963, 6.1292) radius 8.75 clockwise from (-3.6338, 13.4695) to (-13.1588, 13.4695)
  arc A5 centre (-8.3963, 6.1292) radius 8.75 clockwise from (-3.6338, 13.4695) to (-13.1588, 13.4695)
  circle C1 centre (-8.3963, 6.1292) radius 8.75
  point P25 (-10.2963, -17.1208)
  point P33 (-10.2963, -17.1208)
  point P27 (-6.4963, -12.1208)
  point P34 (-6.4963, -12.1208)
  point P24 (-10.2963, -12.1208)
  point P35 (-10.2963, -12.1208)
  point P26 (-6.4963, -17.1208)
  point P36 (-6.4963, -17.1208)
  point P37 (-8.3963, -14.6208)
  point P42 (-8.3963, -14.6208)
  point P47 (-8.3963, 6.1292)
  point P30 (-8.3963, 6.1292)
  point P28 (-13.1588, 13.4695)
  point P43 (-31.4993, 9.3042)
  point P46 (-31.4993, 2.9542)
  point P38 (-28.4985, -11.4458)
  point P41 (-28.4985, -17.7958)
  coincident P25 P33
  coincident P27 P34
  coincident P24 P35
  coincident P26 P36
  midpoint L23 P37
  horizontal L24
  perpendicular L24 L25
  parallel L24 L26
  parallel L25 L27
  coincident L28 P42
  coincident L29 P42
  coincident P37 P42
  horizontal L30
  perpendicular L30 L31
  parallel L30 L32
  parallel L31 L33
  coincident L34 P47
  coincident L35 P47
  coincident P30 P47
  concentric A5 C1
  coincident P28 C1
  dimension "d189" distance P43 P46 = 6.35
  dimension "d190" distance P38 P41 = 6.35
extrude "Extrude2" add sketch "Sketch22" profile of L9 L10 L19 L20 L21 C1 against normal blind 7.3152
extrude "Extrude3" cut sketch "Sketch22" profile of A4 L13 A5 L30 L32 C1 against normal blind 7.3152
extrude "Extrude4" cut sketch "Sketch22" profile of A1 L13 L24 L26 against normal blind 5.207
extrude "Extrude5" add of existing geometry blind 0.0064 (= "2.520E-04 in")
extrude "Extrude6" add of existing geometry blind 0.007 (= "2.756E-04 in")
sketch "Sketch23" plane through (0, 0, 8.3168) normal (0, 0, 1) x axis (-1, 0, 0)
  line L1 (-23.1826, 2.9542) -> (-16.55, 2.9542)
  line L2 (-23.1826, -11.4458) -> (-23.1826, 2.9542)
  line L3 (-17.255, -11.4458) -> (-23.1826, -11.4458)
  line L4 (0.1537, -10.7673) -> (-3.4928, -7.1208)
  line L5 (0.1537, -18.4744) -> (0.1537, -10.7673)
  line L6 (-3.4928, -22.1208) -> (0.1537, -18.4744)
  line L7 (-23.1826, -17.7958) -> (-17.255, -17.7958)
  line L8 (-23.1826, -27.7521) -> (-23.1826, -17.7958)
  line L9 (-16.8326, -34.1021) -> (-23.1826, -27.7521)
  line L10 (0.0399, -34.1021) -> (-16.8326, -34.1021)
  line L11 (6.3899, -27.7521) -> (0.0399, -34.1021)
  line L12 (6.3899, 19.0104) -> (6.3899, -27.7521)
  line L13 (0.0399, 25.3604) -> (6.3899, 19.0104)
  line L14 (-16.8326, 25.3604) -> (0.0399, 25.3604)
  line L15 (-23.1826, 19.0104) -> (-16.8326, 25.3604)
  line L16 (-23.1826, 9.3042) -> (-23.1826, 19.0104)
  line L17 (-16.55, 9.3042) -> (-23.1826, 9.3042)
  line L18 (6.3899, -27.7521) -> (0.0399, -34.1021)
  line L19 (6.3899, 19.0104) -> (6.3899, -27.7521)
  line L20 (0.0399, 25.3604) -> (6.3899, 19.0104)
  line L21 (-16.8326, 25.3604) -> (0.0399, 25.3604)
  line L22 (-23.1826, 19.0104) -> (-16.8326, 25.3604)
  line L23 (-23.1826, -27.7521) -> (-23.1826, 19.0104)
  line L24 (-16.8326, -34.1021) -> (-23.1826, -27.7521)
  line L25 (0.0399, -34.1021) -> (-16.8326, -34.1021)
  line L26 (0.8337, 14.8742) -> (-17.6263, 14.8742)
  line L27 (0.8337, -23.6158) -> (0.8337, 14.8742)
  line L28 (-17.6263, -23.6158) -> (0.8337, -23.6158)
  line L29 (-17.6263, 14.8742) -> (-17.6263, -23.6158)
  arc A1 centre (-8.3963, 6.1292) radius 8.75 clockwise from (-16.55, 9.3042) to (-16.55, 2.9542)
  arc A2 centre (-9.026, -14.6208) radius 8.8203 clockwise from (-17.255, -11.4458) to (-13.668, -7.1208)
  arc A3 centre (-8.5804, -15.3408) radius 9.6671 clockwise from (-13.668, -7.1208) to (-3.4928, -7.1208)
  arc A4 centre (-8.5804, -13.9008) radius 9.6671 clockwise from (-3.4928, -22.1208) to (-13.668, -22.1208)
  arc A5 centre (-9.026, -14.6208) radius 8.8203 clockwise from (-13.668, -22.1208) to (-17.255, -17.7958)
  circle C1 centre (-3.4963, 20.4292) radius 2.2
  circle C2 centre (-13.2963, 20.4292) radius 2.2
  circle C3 centre (-3.4963, -29.1708) radius 2.2
  circle C4 centre (-13.2963, -29.1708) radius 2.2
extrude "Extrude7" cut sketch "Sketch23" profile of C1 C2 C3 C4 against normal blind 6
delete_face "DeleteFace1"
remove_body "RemoveBody2"
remove_body "RemoveBody3"
remove_body "RemoveBody4"
remove_body "RemoveBody5"
delete_face "DeleteFace1"
delete_face "DeleteFace2"
delete_face "DeleteFace3"
delete_face "DeleteFace4"
position "Position6"
sketch "Sketch24" plane through (0, 0, 28) normal (0, 0, 1) x axis (-1, 0, 0)
  line L1 (6.3899, -27.7521) -> (0.0399, -34.1021)
  line L2 (6.3899, 19.0104) -> (6.3899, -27.7521)
  line L3 (0.0399, 25.3604) -> (6.3899, 19.0104)
  line L4 (-16.8326, 25.3604) -> (0.0399, 25.3604)
  line L5 (-23.1826, 19.0104) -> (-16.8326, 25.3604)
  line L6 (-23.1826, -27.7521) -> (-23.1826, 19.0104)
  line L7 (-16.8326, -34.1021) -> (-23.1826, -27.7521)
  line L8 (0.0399, -34.1021) -> (-16.8326, -34.1021)
  line L9 (0.8337, 14.8742) -> (-17.6263, 14.8742)
  line L10 (0.8337, -23.6158) -> (0.8337, 14.8742)
  line L11 (-17.6263, -23.6158) -> (0.8337, -23.6158)
  line L12 (-17.6263, 14.8742) -> (-17.6263, -23.6158)
  circle C1 centre (-3.4963, -29.1708) radius 1.5
  circle C2 centre (-3.4963, -29.1708) radius 1.5
  concentric C1 C2
  dimension "d205" diameter C2 = 3
extrude "Extrude1" cut sketch "Sketch24" profile of C2 against normal blind 43.18
mirror "Mirror1" mirrorStitchTolerance 0.1016
mirror "Mirror2" mirrorStitchTolerance 0.1016
extrude "Extrude8" cut of existing geometry blind -25.4
sketch "Sketch1" plane through (0, 0, 0) normal (0, 0, 1) x axis (1, 0, 0)
  circle C1 centre (0, 0) radius 2.45
  circle C2 centre (0, 0) radius 1.5
  circle C3 centre (0, 0) radius 1.95
  point P1 (0, 0)
  point P2 (0, 0)
  coincident P1 P2
  concentric C1 C2
  concentric C1 C3
  dimension "d1_3" diameter C1 = 4.9
  dimension "d2_3" diameter C2 = 3
  dimension "d3_3" diameter C3 = 3.9
extrude "Extrude1" new body sketch "Sketch1" distance 0.7 (= "( 1.4 / 2 ) * 1 mm") named "d4_3"
extrude "Extrude2" add sketch "Sketch1" profile of C2 C3 distance 3.3 (= "5 mm - 1.7 mm") named "d6_3"
extrude "Extrude3" of existing geometry blind 1.7 named "d9_3"
extrude "Extrude4" add of existing geometry blind 1.7 named "d11_3"
mirror "Mirror1" mirrorStitchTolerance 0.1 named "d14_2"
extrude "Extrude5" new body sketch "Sketch1" profile of C2 C3 distance 3 named "d15_2"
extrude "Extrude6" sketch "Sketch1" blind -1.8 named "d18_2"
mirror "Mirror2" mirrorStitchTolerance 0.1 named "d21_2"
move "Move1"
remove_body "RemoveBody1"
extrude "Extrude9" cut of existing geometry blind -0.4826 (= "10 mm - 0.4127007874015741 in")
position "Position7"
mirror "Mirror3" mirrorStitchTolerance 0.1016
mirror "Mirror4" mirrorStitchTolerance 0.1016
copy_paste "CutPaste6"
offset_faces "OffsetFaces1" distance -3.175
delete_face "DeleteFace2"
delete_face "DeleteFace3"
delete_face "DeleteFace4"
chamfer "Chamfer1" distance 4.7625
remove_instance "RemoveInstance1"
offset_faces "OffsetFaces2" distance -0.2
